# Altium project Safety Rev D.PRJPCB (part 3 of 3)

## Sheet SB_PG7.SCHDOC: (Title)
size B; PageSetup: Record=PageOptions|CenterHorizontal=True|CenterVertical=True|PrintScale=1.09|XCorrection=1.00|YCorrection=1.00|PrintKind=0|BorderSize=5000000|LeftOffset=0|BottomOffset=0|Orientation=2|PaperLength=1000|PaperWidth=1000|Scale=100|PaperSource=7|PrintQuality=-4|MediaType=1|DitherType=10|PaperKind=11x17|PrintScaleMode=1; Engineer: (Engineer); Organization: Institute for Astronomy; Address1: 640 N. Aohoku Place; Address2: Hilo, HI 96720; DocumentNumber: T3-2070; Revision: D; SheetNumber: 7; SheetTotal: 16
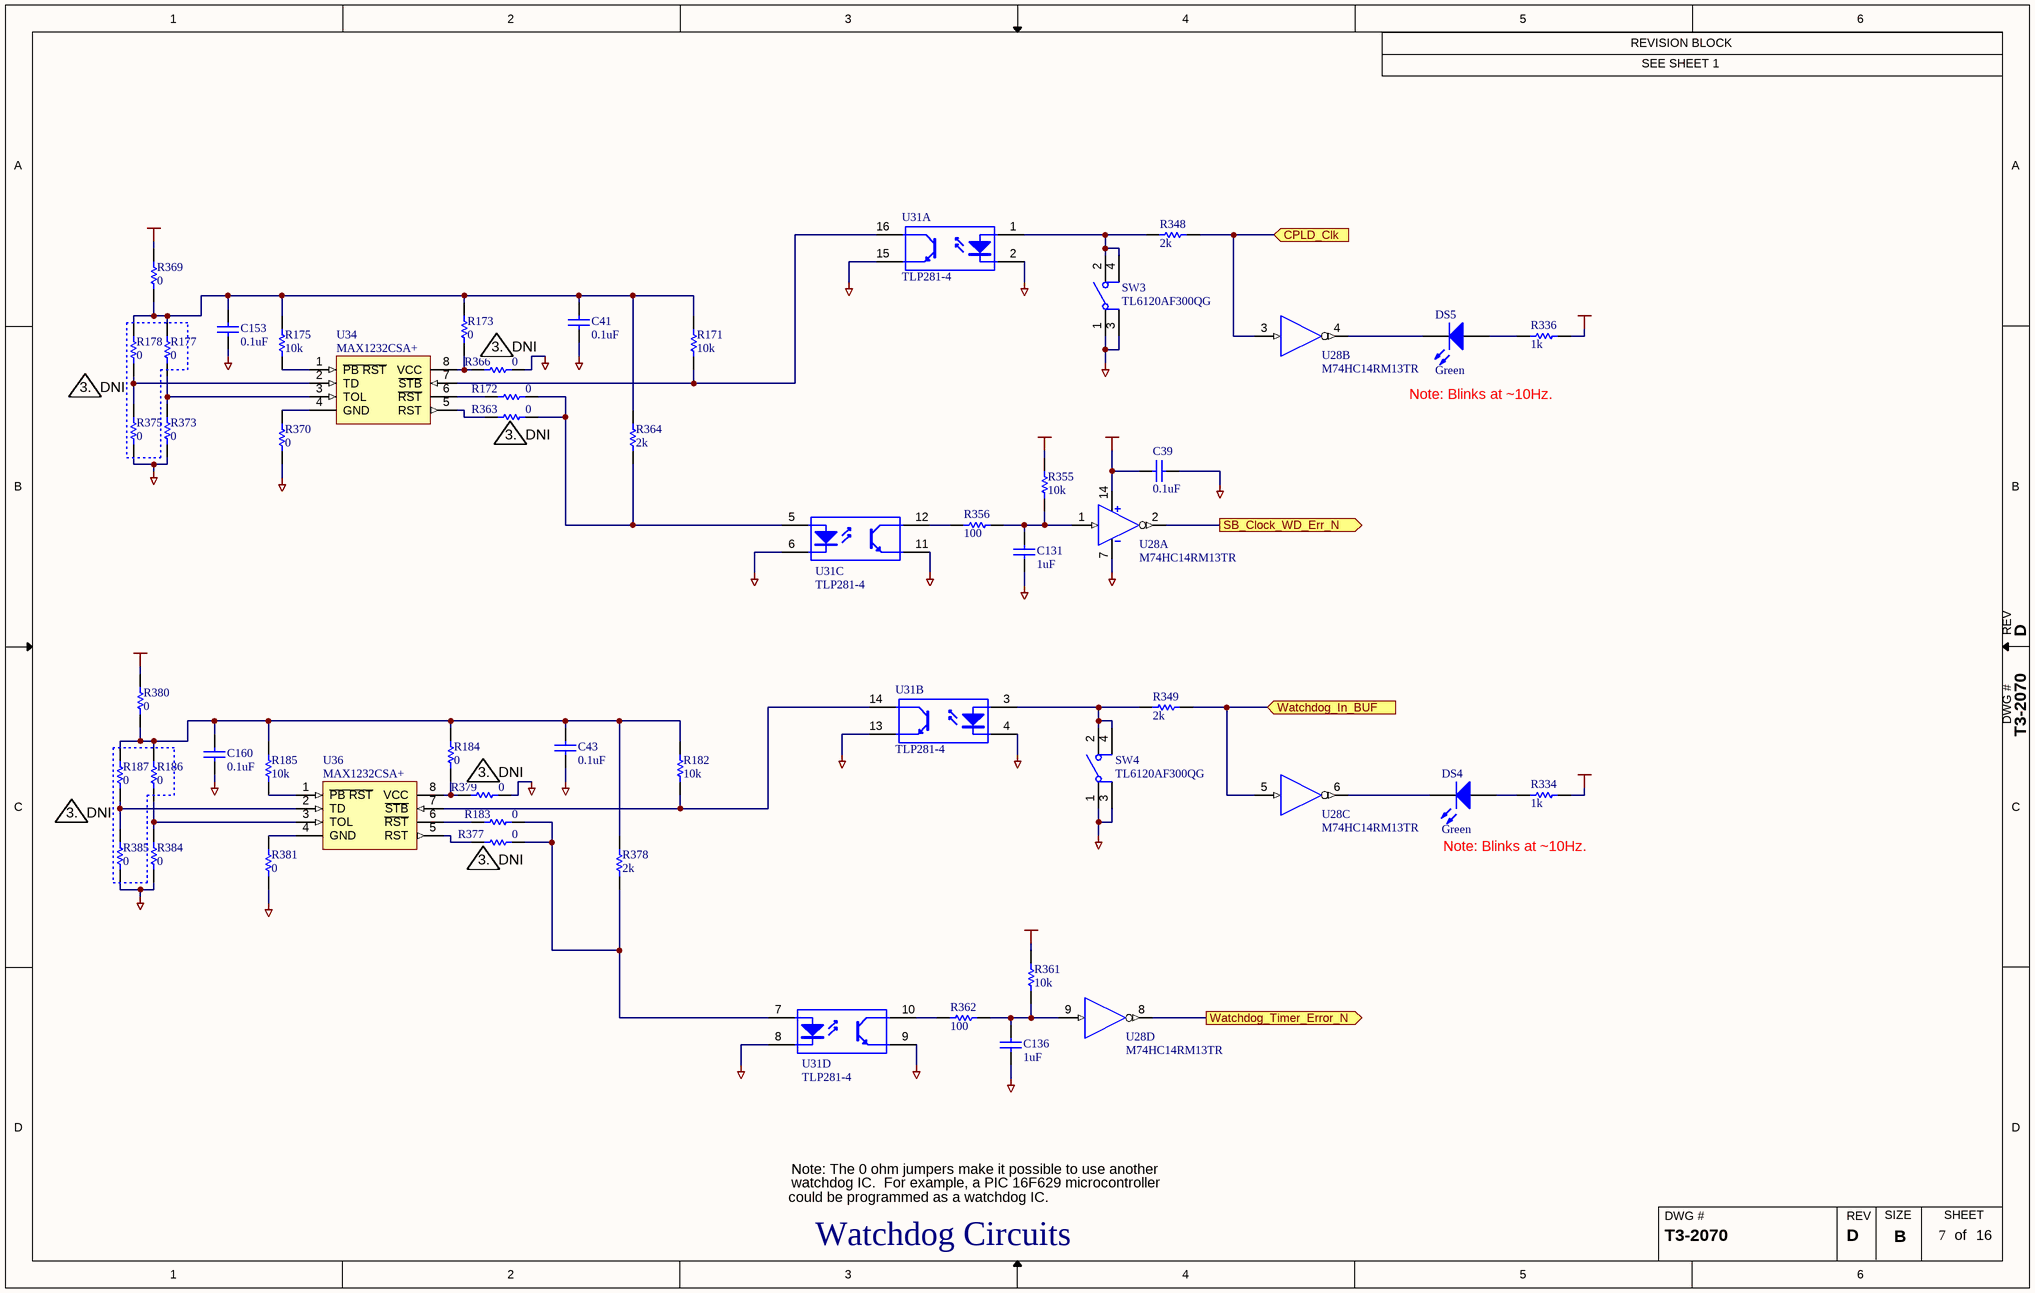
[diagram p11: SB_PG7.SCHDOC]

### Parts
(Parts that share a designator on the sheet are numbered #1, #2 ... from top to bottom, then left to right.)
C39  0.1uF  [1206]
C41  0.1uF  [1206]
C43  0.1uF  [1206]
C131  1uF  [1206]
C136  1uF  [1206]
C153  0.1uF  [1206]
C160  0.1uF  [1206]
DS4  value Green  [LED_1210]  (hidden comment: LTST-C930KGKT)
DS5  value Green  [LED_1210]  (hidden comment: LTST-C930KGKT)
Flag?#41  Flag#: 3.  Note: DNI  (graphical)
Flag?#42  Flag#: 3.  Note: DNI  (graphical)
Flag?#43  Flag#: 3.  Note: DNI  (graphical)
Flag?#44  Flag#: 3.  Note: DNI  (graphical)
Flag?#45  Flag#: 3.  Note: DNI  (graphical)
Flag?#46  Flag#: 3.  Note: DNI  (graphical)
R171  value 10k  [1206]  (hidden comment: 10000)
R172  value 0  [1206]  (hidden comment: 0_jumper)
R173  value 0  [1206]  (hidden comment: 0_jumper)
R175  value 10k  [1206]  (hidden comment: 10000)
R177  value 0  [1206]  (hidden comment: 0_jumper)  (no BOM)
R178  value 0  [1206]  (hidden comment: 0_jumper)  (no BOM)
R182  value 10k  [1206]  (hidden comment: 10000)
R183  value 0  [1206]  (hidden comment: 0_jumper)
R184  value 0  [1206]  (hidden comment: 0_jumper)
R185  value 10k  [1206]  (hidden comment: 10000)
R186  value 0  [1206]  (hidden comment: 0_jumper)  (no BOM)
R187  value 0  [1206]  (hidden comment: 0_jumper)  (no BOM)
R334  value 1k  [1206]  (hidden comment: 1000)
R336  value 1k  [1206]  (hidden comment: 1000)
R348  value 2k  [1206]  (hidden comment: 2000)
R349  value 2k  [1206]  (hidden comment: 2000)
R355  value 10k  [1206]  (hidden comment: 10000)
R356  100  [1206]
R361  value 10k  [1206]  (hidden comment: 10000)
R362  100  [1206]
R363  value 0  [1206]  (hidden comment: 0_jumper)  (no BOM)
R364  value 2k  [1206]  (hidden comment: 2000)
R366  value 0  [1206]  (hidden comment: 0_jumper)  (no BOM)
R369  value 0  [1206]  (hidden comment: 0_jumper)
R370  value 0  [1206]  (hidden comment: 0_jumper)
R373  value 0  [1206]  (hidden comment: 0_jumper)
R375  value 0  [1206]  (hidden comment: 0_jumper)  (no BOM)
R377  value 0  [1206]  (hidden comment: 0_jumper)  (no BOM)
R378  value 2k  [1206]  (hidden comment: 2000)
R379  value 0  [1206]  (hidden comment: 0_jumper)  (no BOM)
R380  value 0  [1206]  (hidden comment: 0_jumper)
R381  value 0  [1206]  (hidden comment: 0_jumper)
R384  value 0  [1206]  (hidden comment: 0_jumper)
R385  value 0  [1206]  (hidden comment: 0_jumper)  (no BOM)
SW3  TL6120AF300QG  [SWITCH_TL6120AF300QG]
SW4  TL6120AF300QG  [SWITCH_TL6120AF300QG]
U28  M74HC14RM13TR  [SOIC_14_Narrow]  (parts A,B,C,D of 6)
U31  TLP281-4  [SOIC_16_C5.85]  (parts A,B,C,D of 4)
U34  Part Number: MAX1232CSA+  [SOIC_8_NARROW]  (hidden comment: MAX1232ESA+)
U36  Part Number: MAX1232CSA+  [SOIC_8_NARROW]  (hidden comment: MAX1232ESA+)

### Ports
CPLD_Clk (in), SB_Clock_WD_Err_N (out), Watchdog_In_BUF (in), Watchdog_Timer_Error_N (out)

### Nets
+5V_DIG: C39.2 R334.2 R336.2 R355.2 R361.2 U28.14(VDD)
+5V_WD: R369.2 R380.2
DGND: C39.1 C131.1 C136.1 SW3.1(COMMON) SW3.3(COMMON) SW4.1(COMMON) SW4.3(COMMON) U28.7(GND) U31.2(K) U31.4(K) U31.9(E) U31.11(E)
WDGND: C41.1 C43.1 C153.1 C160.1 R366.1 R370.1 R373.1 R375.1 R379.1 R381.1 R384.1 R385.1 U31.6(K) U31.8(K) U31.13(E) U31.15(E)
CPLD_Clk: R348.1 U28.3(IN) ; port CPLD_Clk
SB_Clock_WD_Err_N: U28.2(~{OUT}) ; port SB_Clock_WD_Err_N
Watchdog_In_BUF: R349.1 U28.5(IN) ; port Watchdog_In_BUF
Watchdog_Timer_Error_N: U28.8(~{OUT}) ; port Watchdog_Timer_Error_N
NetC41_2: C41.2 C153.2 R171.2 R173.2 R175.2 R177.2 R178.2 R364.2 R369.1
NetC43_2: C43.2 C160.2 R182.2 R184.2 R185.2 R186.2 R187.2 R378.2 R380.1
NetC131_2: C131.2 R355.1 R356.1 U28.1(IN)
NetC136_2: C136.2 R361.1 R362.1 U28.9(IN)
NetDS4_A: DS4.A R334.1
NetDS4_K: DS4.K U28.6(~{OUT})
NetDS5_A: DS5.A R336.1
NetDS5_K: DS5.K U28.4(~{OUT})
NetR171_1: R171.1 U31.16(C) U34.7(~{STB})
NetR172_1: R172.1 R363.1 R364.1 U31.5(A)
NetR172_2: R172.2 U34.6(~{RST})
NetR173_1: R173.1 R366.2 U34.8(VCC)
NetR175_1: R175.1 U34.1(~{PB_RST})
NetR177_1: R177.1 R373.2 U34.3(TOL)
NetR178_1: R178.1 R375.2 U34.2(TD)
NetR182_1: R182.1 U31.14(C) U36.7(~{STB})
NetR183_1: R183.1 R377.1 R378.1 U31.7(A)
NetR183_2: R183.2 U36.6(~{RST})
NetR184_1: R184.1 R379.2 U36.8(VCC)
NetR185_1: R185.1 U36.1(~{PB_RST})
NetR186_1: R186.1 R384.2 U36.3(TOL)
NetR187_1: R187.1 R385.2 U36.2(TD)
NetR348_2: R348.2 SW3.2(NO) SW3.4(NO) U31.1(A)
NetR349_2: R349.2 SW4.2(NO) SW4.4(NO) U31.3(A)
NetR356_2: R356.2 U31.12(C)
NetR362_2: R362.2 U31.10(C)
NetR363_2: R363.2 U34.5(RST)
NetR370_2: R370.2 U34.4(GND)
NetR377_2: R377.2 U36.5(RST)
NetR381_2: R381.2 U36.4(GND)

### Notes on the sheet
- Note: Blinks at
  0Hz.
- Note: The 0 ohm jumpers make it possible to use another
- could be programmed as a watchdog IC.
- watchdog IC.  For example, a PIC 16F629 microcontroller
- Watchdog Circuits

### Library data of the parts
C39 C41 C43 C153 C160 = 0.1uF: Ceramic Chip Capacitor, 0.1uF, 50V, 10%, X7R; Part Number: C1206C104K5RACTU; Manufacturer: Kemet; BOM_IGNORE: False
C131 C136 = 1uF: Ceramic Chip Capacitor, 1uF, 50V, 10%, X7R; Part Number: C1206F105K5RACTU; Manufacturer: Kemet; BOM_IGNORE: False
DS4 DS5 = LTST-C930KGKT: LED, Green, Dome, 1210 SMD; Manufacturer: Lite-On Inc; BOM_IGNORE: FALSE
Flag?#41-Flag?#46 = Flag
R171 R175 R182 R185 R355 R361 = 10000: Thick Film Chip Resistor, 10k Ohm, 1% Tolerance, 1206 Size, 0.25 W; Part Number: ERJ-8ENF1002V; Manufacturer: Panasonic; Power Rating: 0.25W
R172 R173 R177 R178 R183 R184 R186 R187 R363 R366 R369 R370 R373 R375 R377 R379-R381 R384 R385 = 0_jumper: Thick Film Chip Resistor, 0 Ohm, 1206 Size, 0.25 W; Part Number: ERJ-8GEY0R00V; Manufacturer: Panasonic; Tolerance: 1%; Power Rating: 0.25W
R334 R336 = 1000: Thick Film Chip Resistor, 1k Ohm, 1% Tolerance, 1206 Size, 0.25 W; Part Number: ERJ-8ENF1001V; Manufacturer: Panasonic; Power Rating: 0.25W
R348 R349 R364 R378 = 2000: Thick Film Chip Resistor, 2k Ohm, 1% Tolerance, 1206 Size, 0.25 W; Part Number: ERJ-8ENF2001V; Manufacturer: Panasonic; Power Rating: 0.25W
R356 R362 = 100: Thick Film Chip Resistor, 100 Ohm, 1% Tolerance, 1206 Size, 0.25 W; Part Number: ERJ-8ENF1000V; Manufacturer: Panasonic; Power Rating: 0.25W
SW3 SW4 = TL6120AF300QG: Switch, Tactile, SPST, NO; Manufacturer: E-Switch
U28 = M74HC14RM13TR: Hex Schmitt-Trigger Inverter; Manufacturer: STMicroelectronics
U31 = TLP281-4: Photocoupler; Manufacturer: Toshiba
U34 U36 = MAX1232ESA+: IC MPU SUPERVISORY CIRCUIT 8SOIC; Manufacturer: Maxim

## Sheet SB_PG8.SCHDOC: (Title)
size B; PageSetup: Record=PageOptions|CenterHorizontal=True|CenterVertical=True|PrintScale=1.09|XCorrection=1.00|YCorrection=1.00|PrintKind=0|BorderSize=5000000|LeftOffset=0|BottomOffset=0|Orientation=2|PaperLength=1000|PaperWidth=1000|Scale=100|PaperSource=7|PrintQuality=-4|MediaType=1|DitherType=10|PaperKind=11x17|PrintScaleMode=1; Engineer: (Engineer); Organization: Institute for Astronomy; Address1: 640 N. Aohoku Place; Address2: Hilo, HI 96720; DocumentNumber: T3-2070; Revision: D; SheetNumber: 8; SheetTotal: 16
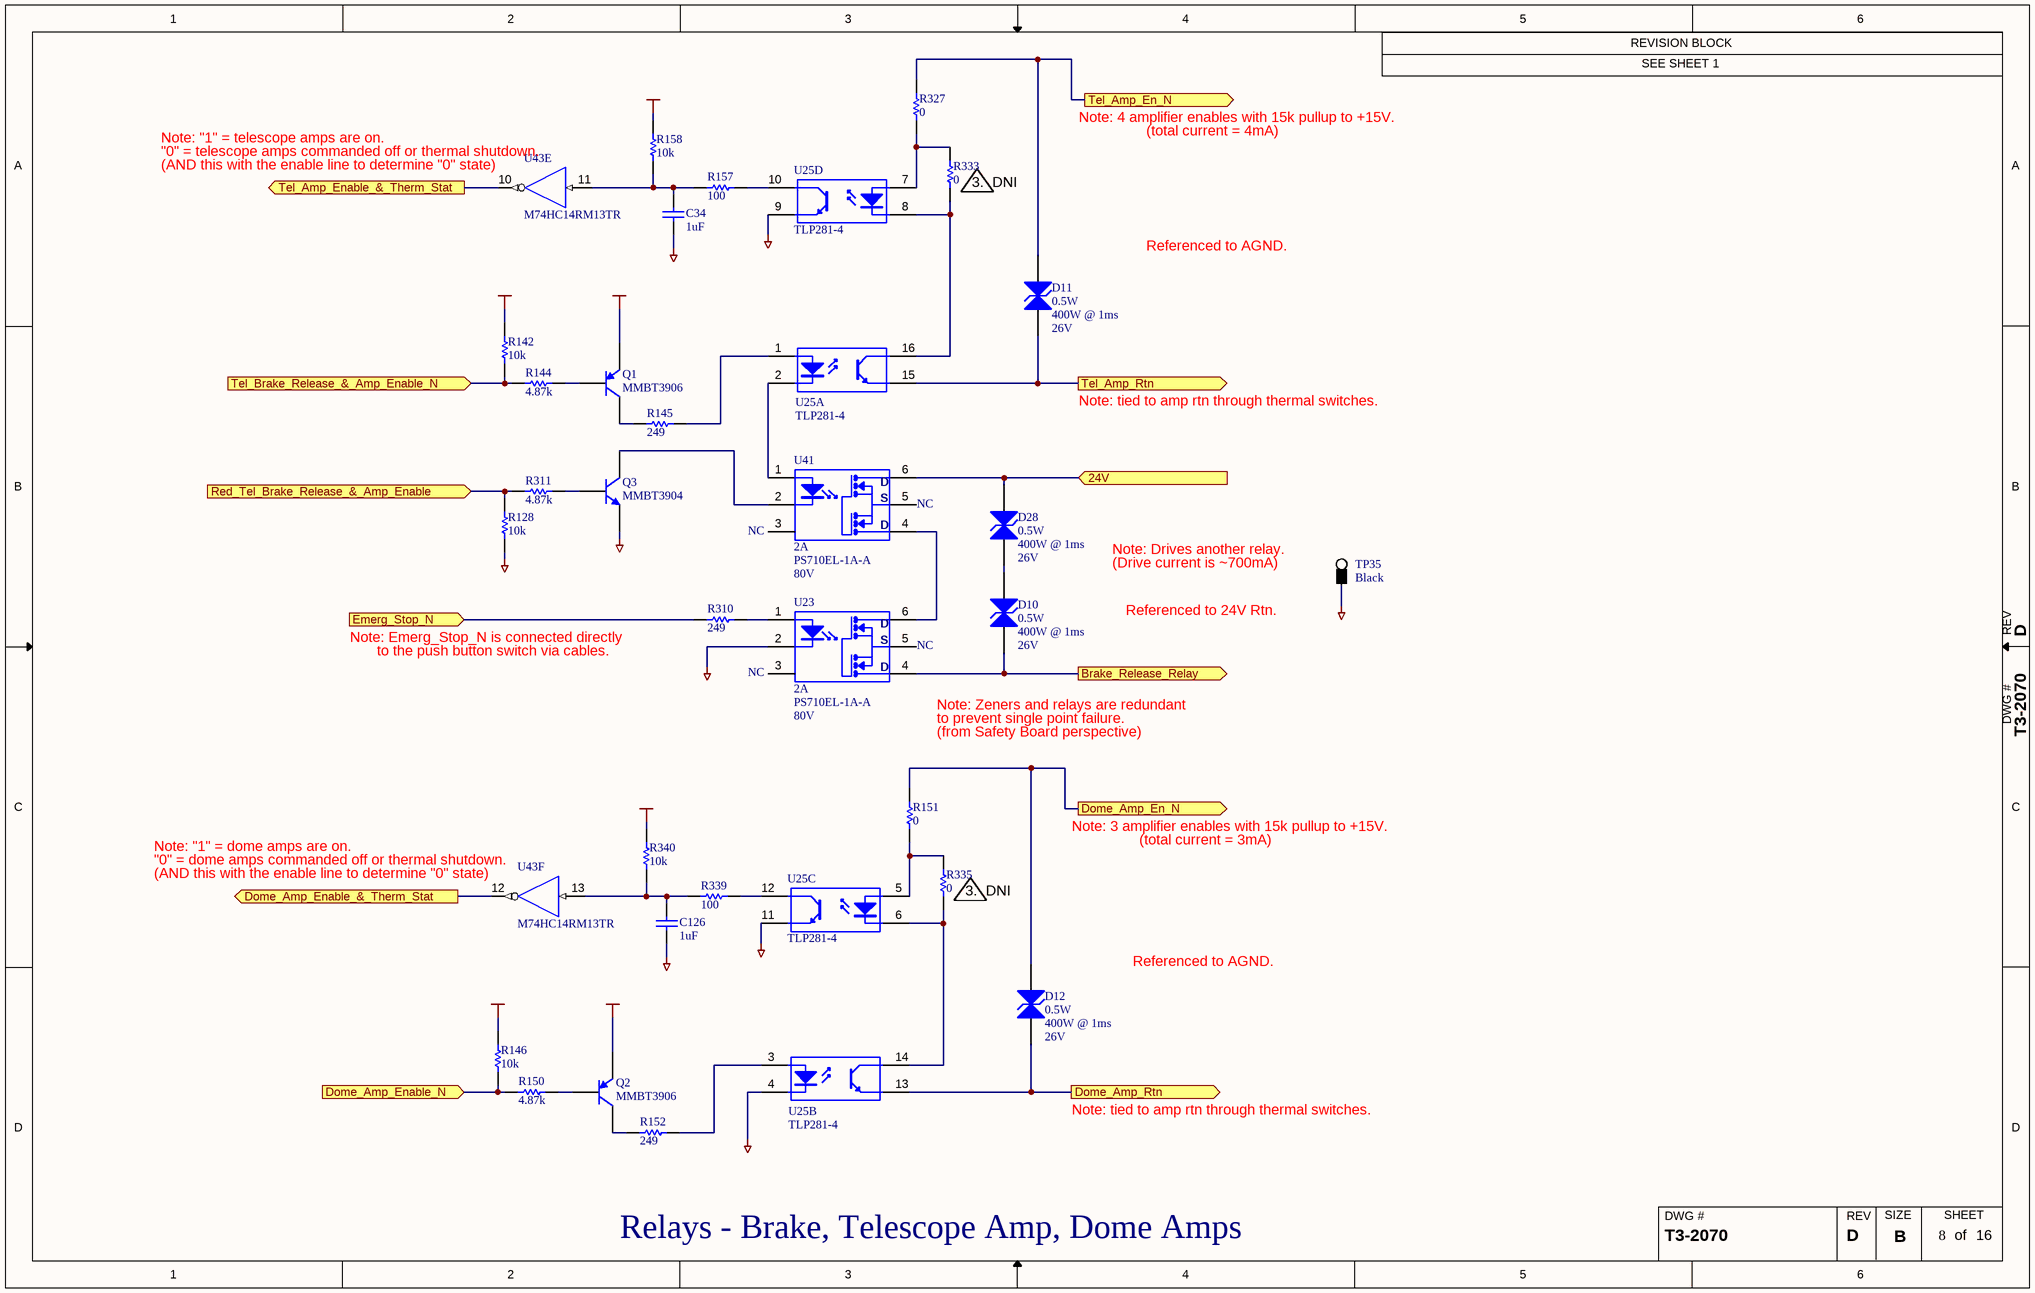
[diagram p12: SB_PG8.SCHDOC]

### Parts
(Parts that share a designator on the sheet are numbered #1, #2 ... from top to bottom, then left to right.)
C34  1uF  [1206]
C126  1uF  [1206]
D10  value 26V  Power: 0.5W  Peak Power: 400W @ 1ms  [DO-214AC (SMA)]  (hidden comment: SMAJ26CA)
D11  value 26V  Power: 0.5W  Peak Power: 400W @ 1ms  [DO-214AC (SMA)]  (hidden comment: SMAJ26CA)
D12  value 26V  Power: 0.5W  Peak Power: 400W @ 1ms  [DO-214AC (SMA)]  (hidden comment: SMAJ26CA)
D28  value 26V  Power: 0.5W  Peak Power: 400W @ 1ms  [DO-214AC (SMA)]  (hidden comment: SMAJ26CA)
Flag?#47  Flag#: 3.  Note: DNI  (graphical)
Flag?#48  Flag#: 3.  Note: DNI  (graphical)
Q1  MMBT3906  [SOT23]
Q2  MMBT3906  [SOT23]
Q3  MMBT3904  [SOT23]
R128  value 10k  [1206]  (hidden comment: 10000)
R142  value 10k  [1206]  (hidden comment: 10000)
R144  value 4.87k  [1206]  (hidden comment: 4870)
R145  249  [1206]
R146  value 10k  [1206]  (hidden comment: 10000)
R150  value 4.87k  [1206]  (hidden comment: 4870)
R151  value 0  [1206]  (hidden comment: 0_jumper)
R152  249  [1206]
R157  100  [1206]
R158  value 10k  [1206]  (hidden comment: 10000)
R310  249  [1206]
R311  value 4.87k  [1206]  (hidden comment: 4870)
R327  value 0  [1206]  (hidden comment: 0_jumper)
R333  value 0  [1206]  (hidden comment: 0_jumper)  (no BOM)
R335  value 0  [1206]  (hidden comment: 0_jumper)  (no BOM)
R339  100  [1206]
R340  value 10k  [1206]  (hidden comment: 10000)
TP35  value Black  [TP_COMPACT]  (hidden comment: TP_5006)
U23  Current: 2A  Voltage: 80V  [SO_6_254P]  (hidden comment: PS710EL-1A-A)
U25  TLP281-4  [SOIC_16_C5.85]  (parts A,B,C,D of 4)
U41  Current: 2A  Voltage: 80V  [SO_6_254P]  (hidden comment: PS710EL-1A-A)
U43  M74HC14RM13TR  [SOIC_14_Narrow]  (parts E,F of 6)

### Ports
24V (in), Brake_Release_Relay (out), Dome_Amp_En_N (out), Dome_Amp_Enable_&_Therm_Stat (out), Dome_Amp_Enable_N (in), Dome_Amp_Rtn (out), Emerg_Stop_N (in), Red_Tel_Brake_Release_&_Amp_Enable (in), Tel_Amp_En_N (out), Tel_Amp_Enable_&_Therm_Stat (out), Tel_Amp_Rtn (out), Tel_Brake_Release_&_Amp_Enable_N (in)

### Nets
24VGND: TP35.1
+5V_DIG: Q1.2(E) Q2.2(E) R142.1 R146.2 R158.2 R340.2
DGND: C34.1 C126.1 Q3.2(E) R128.2 U25.4(K) U25.9(E) U25.11(E)
SEGND: U23.2(K)
24V: D28.K U41.6(DRAIN) ; port 24V
Brake Enable Relay: D10.A U23.4(DRAIN) ; port Brake_Release_Relay
Dome Amp: D12.K R151.1 ; port Dome_Amp_En_N
Dome Amp Ret: D12.A U25.13(E) ; port Dome_Amp_Rtn
Dome_Amp_Enable_&_Therm_Stat: U43.12(~{OUT}) ; port Dome_Amp_Enable_&_Therm_Stat
Dome_Amp_Enable_N: R146.1 R150.2 ; port Dome_Amp_Enable_N
Emerg Stop: R310.2 ; port Emerg_Stop_N
Red_Tel_Brake_Release_&_Amp_Enable: R128.1 R311.2 ; port Red_Tel_Brake_Release_&_Amp_Enable
Tel Amp: D11.K R327.1 ; port Tel_Amp_En_N
Tel Amp Ret: D11.A U25.15(E) ; port Tel_Amp_Rtn
Tel_Amp_Enable_&_Therm_Stat: U43.10(~{OUT}) ; port Tel_Amp_Enable_&_Therm_Stat
Tel_Brake_Release_&_Amp_Enable_N: R142.2 R144.2 ; port Tel_Brake_Release_&_Amp_Enable_N
NetC34_2: C34.2 R157.2 R158.1 U43.11(IN)
NetC126_2: C126.2 R339.2 R340.1 U43.13(IN)
NetD10_K: D10.K D28.A
NetQ1_1: Q1.1(B) R144.1
NetQ1_3: Q1.3(C) R145.2
NetQ2_1: Q2.1(B) R150.1
NetQ2_3: Q2.3(C) R152.2
NetQ3_1: Q3.1(B) R311.1
NetQ3_3: Q3.3(C) U41.2(K)
NetR145_1: R145.1 U25.1(A)
NetR151_2: R151.2 R335.1 U25.5(A)
NetR152_1: R152.1 U25.3(A)
NetR157_1: R157.1 U25.10(C)
NetR310_1: R310.1 U23.1(A)
NetR327_2: R327.2 R333.1 U25.7(A)
NetR333_2: R333.2 U25.8(K) U25.16(C)
NetR335_2: R335.2 U25.6(K) U25.14(C)
NetR339_1: R339.1 U25.12(C)
NetU23_6: U23.6(DRAIN) U41.4(DRAIN)
NetU25_2: U25.2(K) U41.1(A)

Not connected (* = marked no-connect by the designer): U23 3(NC) 5(SOURCE); U41 3(NC) 5(SOURCE)

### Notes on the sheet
- Note: "1" = telescope amps are on.
- (near U43) "0" = telescope amps commanded off or thermal shutdown.
- Note: 4 amplifier enables with 15k pullup to +15V.
- (total current = 4mA)
- (near U43) (AND this with the enable line to determine "0" state)
- Referenced to AGND.
- Note: tied to amp rtn through thermal switches.
- (near U41) NC
- (near TP35) Note: Drives another relay.
- (near TP35) (Drive current is ~700mA)
- Note: Emerg_Stop_N is connected directly
- Referenced to 24V Rtn.
- to the push button switch via cables.
- NC
- (near U23) NC
- Note: Zeners and relays are redundant
- to prevent single point failure.
- (from Safety Board perspective)
- Note: 3 amplifier enables with 15k pullup to +15V.
- Note: "1" = dome amps are on.
- (near U43) "0" = dome amps commanded off or thermal shutdown.
- (total current = 3mA)
- Relays - Brake, Telescope Amp, Dome Amps

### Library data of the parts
C34 C126 = 1uF: as C131 on sheet SB_PG7
D10-D12 D28 = SMAJ26CA: TVS 400W 26V BIDIRECT SMA; Manufacturer: Diodes Inc.
Flag?#47 Flag?#48 = Flag
Q1 Q2 = MMBT3906: PNP Switching Transistor; Manufacturer: Fairchild Semiconductor
Q3 = MMBT3904: NPN Switching Transistor; Manufacturer: Fairchild Semiconductor
R128 R142 R146 R158 R340 = 10000: as R171 on sheet SB_PG7
R144 R150 R311 = 4870: Thick Film Chip Resistor, 4.87k Ohm, 1% Tolerance, 1206 Size, 0.25 W; Part Number: ERJ-8ENF4871V; Manufacturer: Panasonic; Power Rating: 0.25W
R145 R152 R310 = 249: Thick Film Chip Resistor, 249 Ohm, 1% Tolerance, 1206 Size, 0.25 W; Part Number: ERJ-8ENF2490V; Manufacturer: Panasonic; Power Rating: 0.25W
R151 R327 R333 R335 = 0_jumper: as R172 on sheet SB_PG7
R157 R339 = 100: as R356 on sheet SB_PG7
TP35 = TP_5006: Black, Compact Test Point, Thru Hole, Loop; Part Number: 5006; Manufacturer: Keystone; BOM_IGNORE: FALSE
U23 U41 = PS710EL-1A-A: Solid State Relay, 2A, 80V; Manufacturer: NEC
U25 = TLP281-4: Photocoupler; Manufacturer: Toshiba
U43 = M74HC14RM13TR: as U28 on sheet SB_PG7

## Sheet SB_PG9.SCHDOC: (Title)
size B; PageSetup: Record=PageOptions|CenterHorizontal=True|CenterVertical=True|PrintScale=1.09|XCorrection=1.00|YCorrection=1.00|PrintKind=0|BorderSize=5000000|LeftOffset=0|BottomOffset=0|Orientation=2|PaperLength=1000|PaperWidth=1000|Scale=100|PaperSource=7|PrintQuality=-4|MediaType=1|DitherType=10|PaperKind=11x17|PrintScaleMode=1; Engineer: (Engineer); Organization: Institute for Astronomy; Address1: 640 N. Aohoku Place; Address2: Hilo, HI 96720; DocumentNumber: T3-2070; Revision: D; SheetNumber: 9; SheetTotal: 16
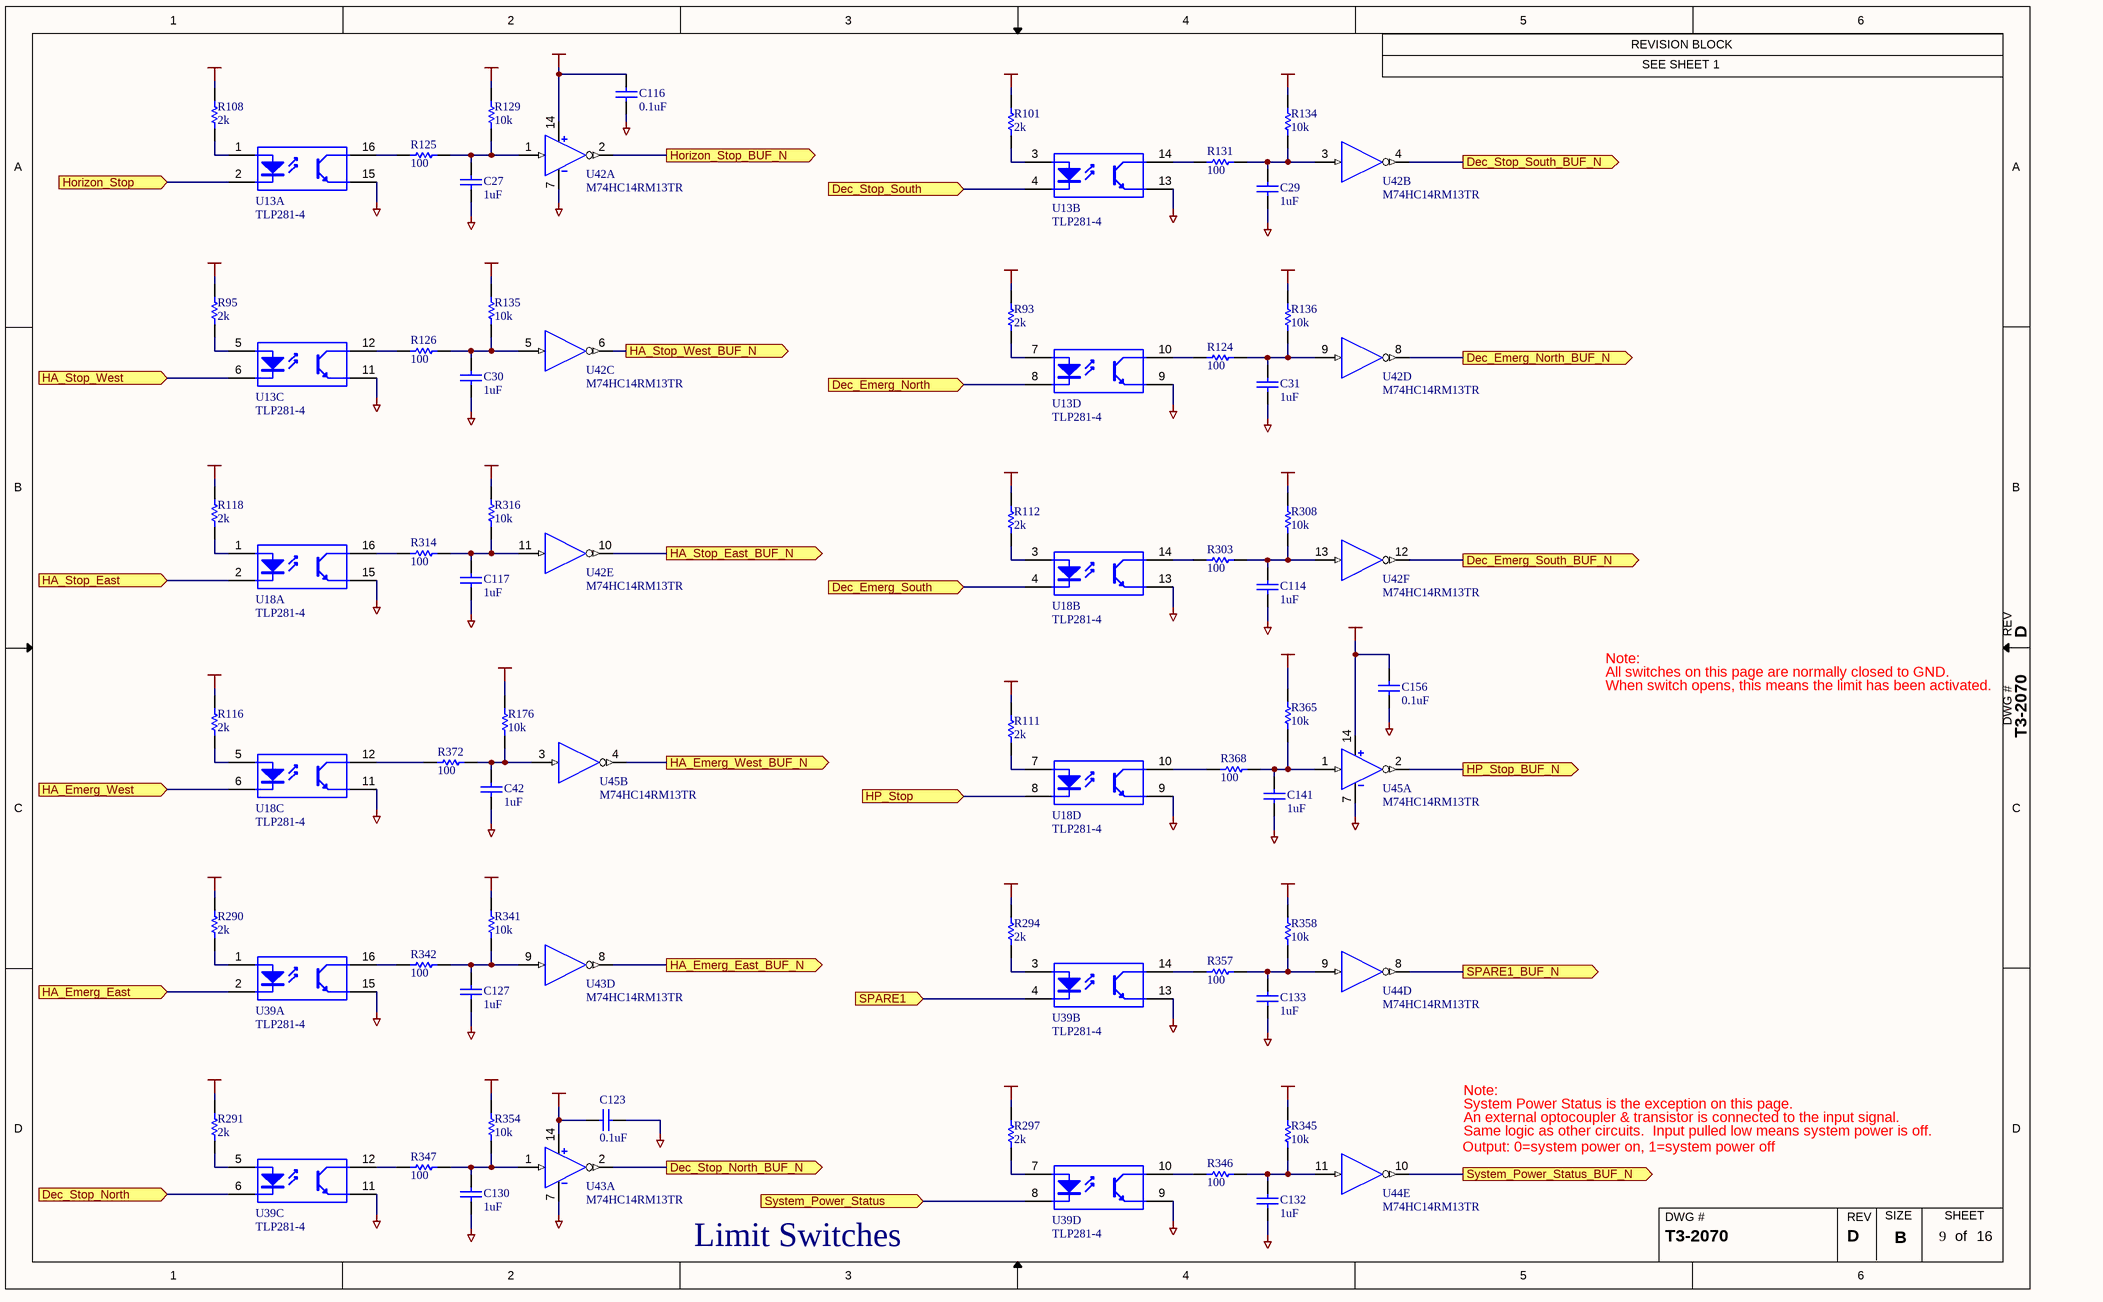
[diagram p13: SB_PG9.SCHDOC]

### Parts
C27  1uF  [1206]
C29  1uF  [1206]
C30  1uF  [1206]
C31  1uF  [1206]
C42  1uF  [1206]
C114  1uF  [1206]
C116  0.1uF  [1206]
C117  1uF  [1206]
C123  0.1uF  [1206]
C127  1uF  [1206]
C130  1uF  [1206]
C132  1uF  [1206]
C133  1uF  [1206]
C141  1uF  [1206]
C156  0.1uF  [1206]
R93  value 2k  [1206]  (hidden comment: 2000)
R95  value 2k  [1206]  (hidden comment: 2000)
R101  value 2k  [1206]  (hidden comment: 2000)
R108  value 2k  [1206]  (hidden comment: 2000)
R111  value 2k  [1206]  (hidden comment: 2000)
R112  value 2k  [1206]  (hidden comment: 2000)
R116  value 2k  [1206]  (hidden comment: 2000)
R118  value 2k  [1206]  (hidden comment: 2000)
R124  100  [1206]
R125  100  [1206]
R126  100  [1206]
R129  value 10k  [1206]  (hidden comment: 10000)
R131  100  [1206]
R134  value 10k  [1206]  (hidden comment: 10000)
R135  value 10k  [1206]  (hidden comment: 10000)
R136  value 10k  [1206]  (hidden comment: 10000)
R176  value 10k  [1206]  (hidden comment: 10000)
R290  value 2k  [1206]  (hidden comment: 2000)
R291  value 2k  [1206]  (hidden comment: 2000)
R294  value 2k  [1206]  (hidden comment: 2000)
R297  value 2k  [1206]  (hidden comment: 2000)
R303  100  [1206]
R308  value 10k  [1206]  (hidden comment: 10000)
R314  100  [1206]
R316  value 10k  [1206]  (hidden comment: 10000)
R341  value 10k  [1206]  (hidden comment: 10000)
R342  100  [1206]
R345  value 10k  [1206]  (hidden comment: 10000)
R346  100  [1206]
R347  100  [1206]
R354  value 10k  [1206]  (hidden comment: 10000)
R357  100  [1206]
R358  value 10k  [1206]  (hidden comment: 10000)
R365  value 10k  [1206]  (hidden comment: 10000)
R368  100  [1206]
R372  100  [1206]
U13  TLP281-4  [SOIC_16_C5.85]  (parts A,B,C,D of 4)
U18  TLP281-4  [SOIC_16_C5.85]  (parts A,B,C,D of 4)
U39  TLP281-4  [SOIC_16_C5.85]  (parts A,B,C,D of 4)
U42  M74HC14RM13TR  [SOIC_14_Narrow]  (parts A,B,C,D,E,F of 6)
U43  M74HC14RM13TR  [SOIC_14_Narrow]  (parts A,D of 6)
U44  M74HC14RM13TR  [SOIC_14_Narrow]  (parts D,E of 6)
U45  M74HC14RM13TR  [SOIC_14_Narrow]  (parts A,B of 6)

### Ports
Dec_Emerg_North (in), Dec_Emerg_North_BUF_N (out), Dec_Emerg_South (in), Dec_Emerg_South_BUF_N (out), Dec_Stop_North (in), Dec_Stop_North_BUF_N (out), Dec_Stop_South (in), Dec_Stop_South_BUF_N (out), HA_Emerg_East (in), HA_Emerg_East_BUF_N (out), HA_Emerg_West (in), HA_Emerg_West_BUF_N (out), HA_Stop_East (in), HA_Stop_East_BUF_N (out), HA_Stop_West (in), HA_Stop_West_BUF_N (out), Horizon_Stop (in), Horizon_Stop_BUF_N (out), HP_Stop (in), HP_Stop_BUF_N (out), SPARE1 (in), SPARE1_BUF_N (out), System_Power_Status (in), System_Power_Status_BUF_N (out)

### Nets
+5V_DIG: C116.2 C123.2 C156.2 R129.2 R134.2 R135.2 R136.2 R176.2 R308.2 R316.2 R341.2 R345.2 R354.2 R358.2 R365.2 U42.14(VDD) U43.14(VDD) U45.14(VDD)
+5V_SE: R93.2 R95.2 R101.2 R108.2 R111.2 R112.2 R116.2 R118.2 R290.2 R291.2 R294.2 R297.2
DGND: C27.1 C29.1 C30.1 C31.1 C42.1 C114.1 C116.1 C117.1 C123.1 C127.1 C130.1 C132.1 C133.1 C141.1 C156.1 U13.9(E) U13.11(E) U13.13(E) U13.15(E) U18.9(E) U18.11(E) U18.13(E) U18.15(E) U39.9(E) U39.11(E) U39.13(E) U39.15(E) U42.7(GND) U43.7(GND) U45.7(GND)
Dec Emerg N: U13.8(K) ; port Dec_Emerg_North
Dec Emerg S: U18.4(K) ; port Dec_Emerg_South
Dec Stop N: U39.6(K) ; port Dec_Stop_North
Dec Stop S: U13.4(K) ; port Dec_Stop_South
Dec_Emerg_North_BUF_N: U42.8(~{OUT}) ; port Dec_Emerg_North_BUF_N
Dec_Emerg_South_BUF_N: U42.12(~{OUT}) ; port Dec_Emerg_South_BUF_N
Dec_Stop_North_BUF_N: U43.2(~{OUT}) ; port Dec_Stop_North_BUF_N
Dec_Stop_South_BUF_N: U42.4(~{OUT}) ; port Dec_Stop_South_BUF_N
HA Emerg E: U39.2(K) ; port HA_Emerg_East
HA Emerg W: U18.6(K) ; port HA_Emerg_West
HA Stop E: U18.2(K) ; port HA_Stop_East
HA Stop W: U13.6(K) ; port HA_Stop_West
HA_Emerg_East_BUF_N: U43.8(~{OUT}) ; port HA_Emerg_East_BUF_N
HA_Emerg_West_BUF_N: U45.4(~{OUT}) ; port HA_Emerg_West_BUF_N
HA_Stop_East_BUF_N: U42.10(~{OUT}) ; port HA_Stop_East_BUF_N
HA_Stop_West_BUF_N: U42.6(~{OUT}) ; port HA_Stop_West_BUF_N
Horizon Stop: U13.2(K) ; port Horizon_Stop
Horizon_Stop_BUF_N: U42.2(~{OUT}) ; port Horizon_Stop_BUF_N
HP Stop: U18.8(K) ; port HP_Stop
HP_Stop_BUF_N: U45.2(~{OUT}) ; port HP_Stop_BUF_N
SPARE1_BUF_N: U44.8(~{OUT}) ; port SPARE1_BUF_N
Spare In 1: U39.4(K) ; port SPARE1
System Power Status: U39.8(K) ; port System_Power_Status
System_Power_Status_BUF_N: U44.10(~{OUT}) ; port System_Power_Status_BUF_N
NetC27_2: C27.2 R125.1 R129.1 U42.1(IN)
NetC29_2: C29.2 R131.1 R134.1 U42.3(IN)
NetC30_2: C30.2 R126.1 R135.1 U42.5(IN)
NetC31_2: C31.2 R124.1 R136.1 U42.9(IN)
NetC42_2: C42.2 R176.1 R372.1 U45.3(IN)
NetC114_2: C114.2 R303.1 R308.1 U42.13(IN)
NetC117_2: C117.2 R314.1 R316.1 U42.11(IN)
NetC127_2: C127.2 R341.1 R342.1 U43.9(IN)
NetC130_2: C130.2 R347.1 R354.1 U43.1(IN)
NetC132_2: C132.2 R345.1 R346.1 U44.11(IN)
NetC133_2: C133.2 R357.1 R358.1 U44.9(IN)
NetC141_2: C141.2 R365.1 R368.1 U45.1(IN)
NetR93_1: R93.1 U13.7(A)
NetR95_1: R95.1 U13.5(A)
NetR101_1: R101.1 U13.3(A)
NetR108_1: R108.1 U13.1(A)
NetR111_1: R111.1 U18.7(A)
NetR112_1: R112.1 U18.3(A)
NetR116_1: R116.1 U18.5(A)
NetR118_1: R118.1 U18.1(A)
NetR124_2: R124.2 U13.10(C)
NetR125_2: R125.2 U13.16(C)
NetR126_2: R126.2 U13.12(C)
NetR131_2: R131.2 U13.14(C)
NetR290_1: R290.1 U39.1(A)
NetR291_1: R291.1 U39.5(A)
NetR294_1: R294.1 U39.3(A)
NetR297_1: R297.1 U39.7(A)
NetR303_2: R303.2 U18.14(C)
NetR314_2: R314.2 U18.16(C)
NetR342_2: R342.2 U39.16(C)
NetR346_2: R346.2 U39.10(C)
NetR347_2: R347.2 U39.12(C)
NetR357_2: R357.2 U39.14(C)
NetR368_2: R368.2 U18.10(C)
NetR372_2: R372.2 U18.12(C)

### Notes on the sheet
- All switches on this page are normally closed to GND.
- Note:
- When switch opens, this means the limit has been activated.
- System Power Status is the exception on this page.
- Output: 0=system power on, 1=system power off
- An external optocoupler & transistor is connected to the input signal.
- Same logic as other circuits.  Input pulled low means system power is off.
- Limit Switches

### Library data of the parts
C27 C29-C31 C42 C114 C117 C127 C130 C132 C133 C141 = 1uF: as C131 on sheet SB_PG7
C116 C123 C156 = 0.1uF: as C39 on sheet SB_PG7
R93 R95 R101 R108 R111 R112 R116 R118 R290 R291 R294 R297 = 2000: as R348 on sheet SB_PG7
R124-R126 R131 R303 R314 R342 R346 R347 R357 R368 R372 = 100: as R356 on sheet SB_PG7
R129 R134-R136 R176 R308 R316 R341 R345 R354 R358 R365 = 10000: as R171 on sheet SB_PG7
U13 U18 U39 = TLP281-4: Photocoupler; Manufacturer: Toshiba
U42-U45 = M74HC14RM13TR: as U28 on sheet SB_PG7

## Sheet SB_PG10.SCHDOC: (Title)
size B; PageSetup: Record=PageOptions|CenterHorizontal=True|CenterVertical=True|PrintScale=1.09|XCorrection=1.00|YCorrection=1.00|PrintKind=0|BorderSize=5000000|LeftOffset=0|BottomOffset=0|Orientation=2|PaperLength=1000|PaperWidth=1000|Scale=100|PaperSource=7|PrintQuality=-4|MediaType=1|DitherType=10|PaperKind=11x17|PrintScaleMode=1; Engineer: (Engineer); Organization: Institute for Astronomy; Address1: 640 N. Aohoku Place; Address2: Hilo, HI 96720; DocumentNumber: T3-2070; Revision: D; SheetNumber: 10; SheetTotal: 16
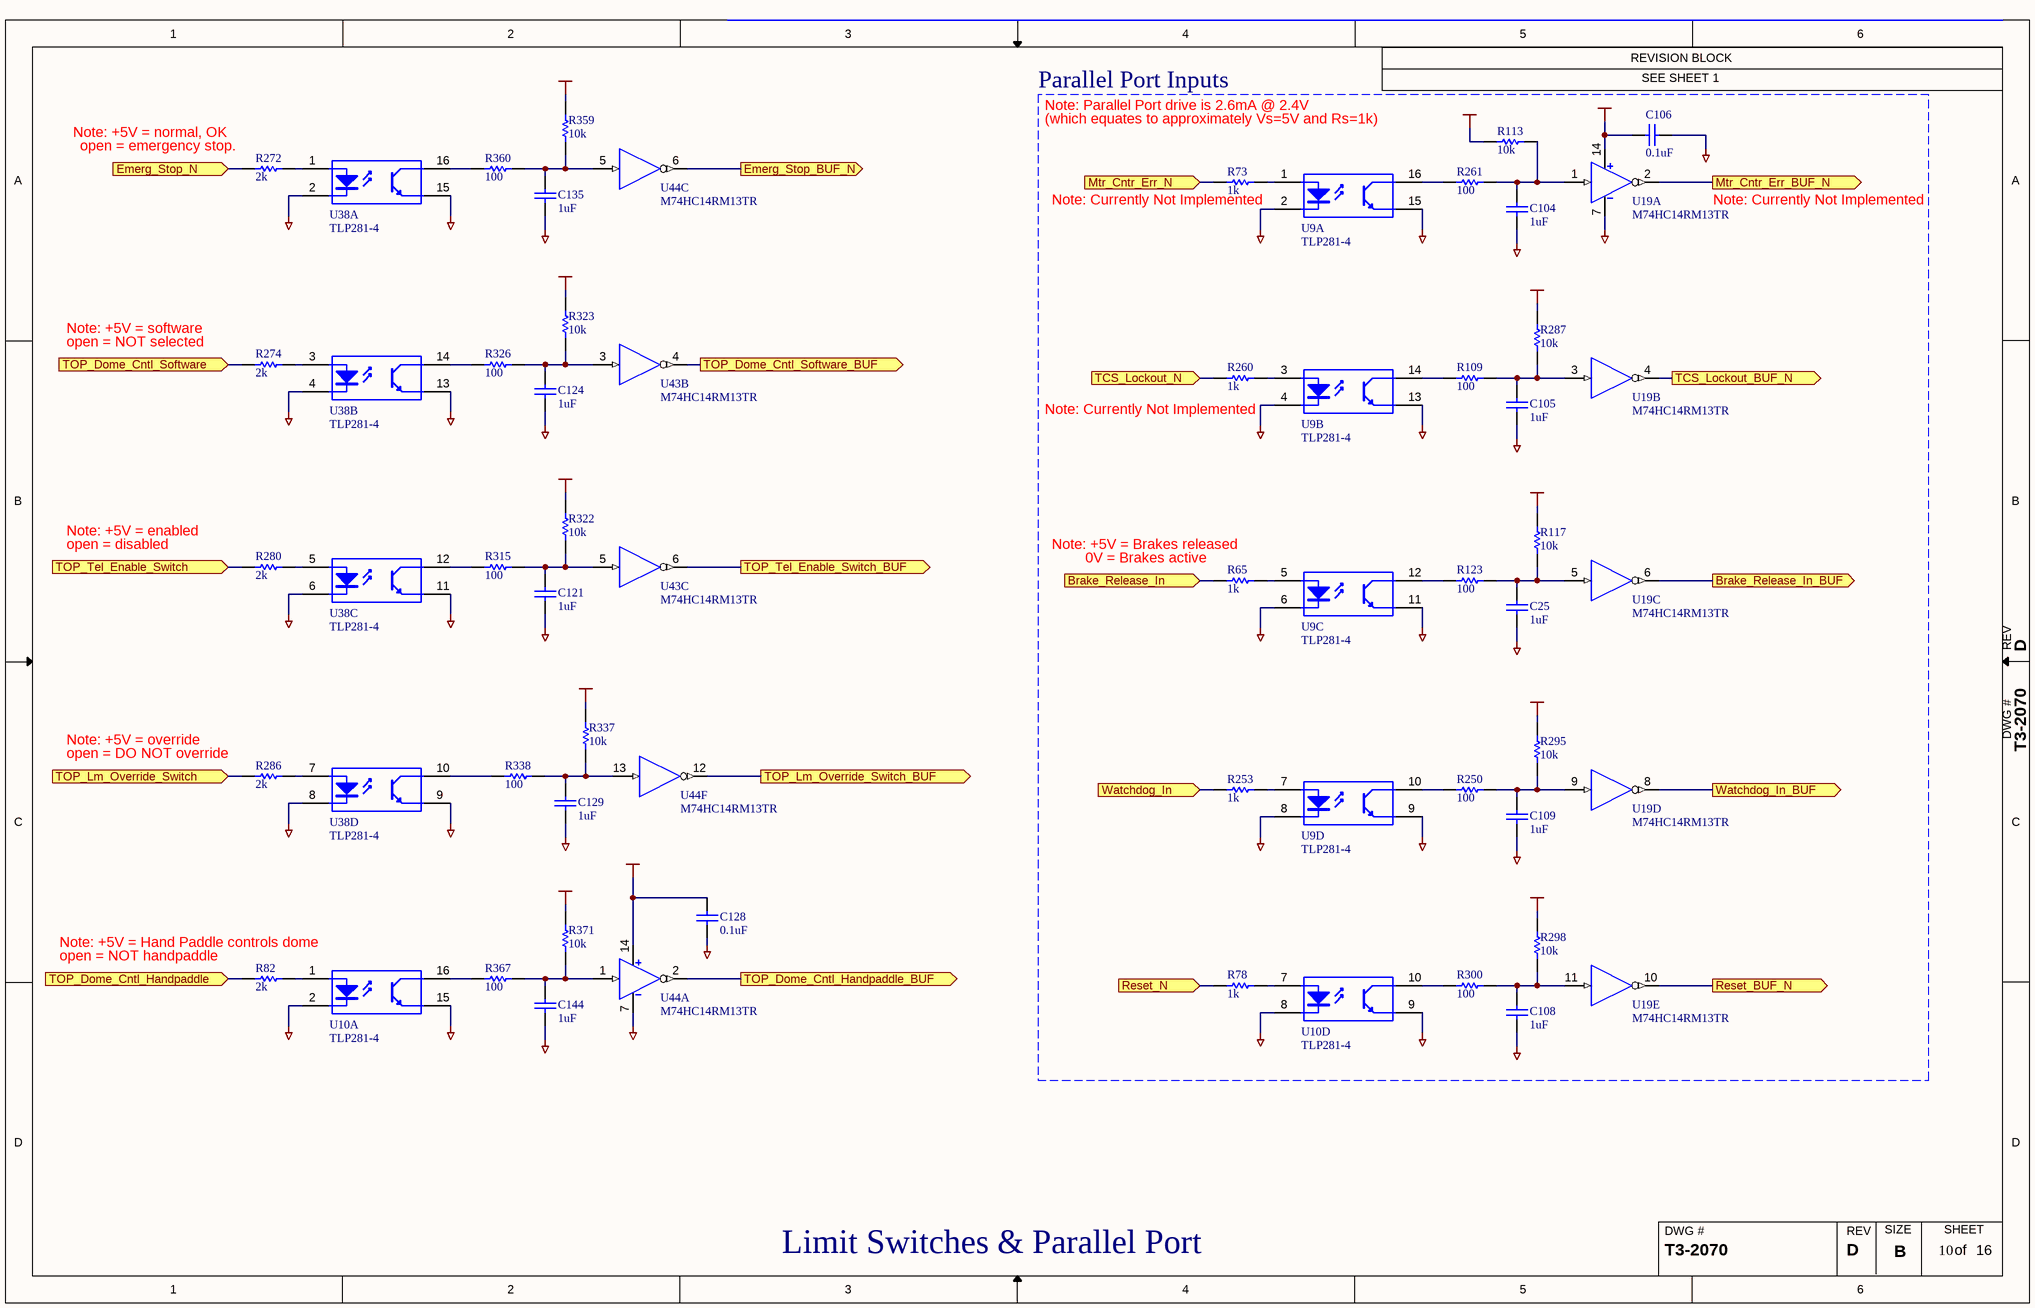
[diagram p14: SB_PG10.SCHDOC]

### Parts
C25  1uF  [1206]
C104  1uF  [1206]
C105  1uF  [1206]
C106  0.1uF  [1206]
C108  1uF  [1206]
C109  1uF  [1206]
C121  1uF  [1206]
C124  1uF  [1206]
C128  0.1uF  [1206]
C129  1uF  [1206]
C135  1uF  [1206]
C144  1uF  [1206]
R65  value 1k  [1206]  (hidden comment: 1000)
R73  value 1k  [1206]  (hidden comment: 1000)
R78  value 1k  [1206]  (hidden comment: 1000)
R82  value 2k  [1206]  (hidden comment: 2000)
R109  100  [1206]
R113  value 10k  [1206]  (hidden comment: 10000)
R117  value 10k  [1206]  (hidden comment: 10000)
R123  100  [1206]
R250  100  [1206]
R253  value 1k  [1206]  (hidden comment: 1000)
R260  value 1k  [1206]  (hidden comment: 1000)
R261  100  [1206]
R272  value 2k  [1206]  (hidden comment: 2000)
R274  value 2k  [1206]  (hidden comment: 2000)
R280  value 2k  [1206]  (hidden comment: 2000)
R286  value 2k  [1206]  (hidden comment: 2000)
R287  value 10k  [1206]  (hidden comment: 10000)
R295  value 10k  [1206]  (hidden comment: 10000)
R298  value 10k  [1206]  (hidden comment: 10000)
R300  100  [1206]
R315  100  [1206]
R322  value 10k  [1206]  (hidden comment: 10000)
R323  value 10k  [1206]  (hidden comment: 10000)
R326  100  [1206]
R337  value 10k  [1206]  (hidden comment: 10000)
R338  100  [1206]
R359  value 10k  [1206]  (hidden comment: 10000)
R360  100  [1206]
R367  100  [1206]
R371  value 10k  [1206]  (hidden comment: 10000)
U9  TLP281-4  [SOIC_16_C5.85]  (parts A,B,C,D of 4)
U10  TLP281-4  [SOIC_16_C5.85]  (parts A,D of 4)
U19  M74HC14RM13TR  [SOIC_14_Narrow]  (parts A,B,C,D,E of 6)
U38  TLP281-4  [SOIC_16_C5.85]  (parts A,B,C,D of 4)
U43  M74HC14RM13TR  [SOIC_14_Narrow]  (parts B,C of 6)
U44  M74HC14RM13TR  [SOIC_14_Narrow]  (parts A,C,F of 6)

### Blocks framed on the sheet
Parallel Port Inputs: C25 C104-C106 C108 C109 R65 R73 R78 R109 R113 R117 R123 R250 R253 R260 R261 R287 R295 R298 R300 U9 U10 U19

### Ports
Brake_Release_In (in), Brake_Release_In_BUF (out), Emerg_Stop_BUF_N (out), Emerg_Stop_N (in), Mtr_Cntr_Err_BUF_N (out), Mtr_Cntr_Err_N (in), Reset_BUF_N (out), Reset_N (in), TCS_Lockout_BUF_N (out), TCS_Lockout_N (in), TOP_Dome_Cntl_Handpaddle (in), TOP_Dome_Cntl_Handpaddle_BUF (out), TOP_Dome_Cntl_Software (in), TOP_Dome_Cntl_Software_BUF (out), TOP_Lm_Override_Switch (in), TOP_Lm_Override_Switch_BUF (out), TOP_Tel_Enable_Switch (in), TOP_Tel_Enable_Switch_BUF (out), Watchdog_In (in), Watchdog_In_BUF (out)

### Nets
+5V_DIG: C106.2 C128.2 R113.2 R117.2 R287.2 R295.2 R298.2 R322.2 R323.2 R337.2 R359.2 R371.2 U19.14(VDD) U44.14(VDD)
DGND: C25.1 C104.1 C105.1 C106.1 C108.1 C109.1 C121.1 C124.1 C128.1 C129.1 C135.1 C144.1 U9.9(E) U9.11(E) U9.13(E) U9.15(E) U10.9(E) U10.15(E) U19.7(GND) U38.9(E) U38.11(E) U38.13(E) U38.15(E) U44.7(GND)
PCGND: U9.2(K) U9.4(K) U9.6(K) U9.8(K) U10.8(K)
SEGND: U10.2(K) U38.2(K) U38.4(K) U38.6(K) U38.8(K)
Brake En In: R65.1 ; port Brake_Release_In
Brake_Release_In_BUF: U19.6(~{OUT}) ; port Brake_Release_In_BUF
Emerg Stop: R272.2 ; port Emerg_Stop_N
Emerg_Stop_BUF_N: U44.6(~{OUT}) ; port Emerg_Stop_BUF_N
Mtr Cntr Err: R73.1 ; port Mtr_Cntr_Err_N
Mtr_Cntr_Err_BUF: U19.2(~{OUT}) ; port Mtr_Cntr_Err_BUF_N
Reset: R78.1 ; port Reset_N
Reset_BUF_N: U19.10(~{OUT}) ; port Reset_BUF_N
TCS Lockout: R260.1 ; port TCS_Lockout_N
TCS_Lockout_BUF_N: U19.4(~{OUT}) ; port TCS_Lockout_BUF_N
TOP DomeCntl Handpaddle: R82.2 ; port TOP_Dome_Cntl_Handpaddle
TOP DomeCntl Software: R274.2 ; port TOP_Dome_Cntl_Software
TOP Lm Override Switch: R286.2 ; port TOP_Lm_Override_Switch
TOP Tel Enable Switch: R280.2 ; port TOP_Tel_Enable_Switch
TOP_Dome_Cntl_Handpaddle_BUF: U44.2(~{OUT}) ; port TOP_Dome_Cntl_Handpaddle_BUF
TOP_Dome_Cntl_Software_BUF: U43.4(~{OUT}) ; port TOP_Dome_Cntl_Software_BUF
TOP_Lm_Override_Switch_BUF: U44.12(~{OUT}) ; port TOP_Lm_Override_Switch_BUF
TOP_Tel_Enable_Switch_BUF: U43.6(~{OUT}) ; port TOP_Tel_Enable_Switch_BUF
Watchdog In: R253.1 ; port Watchdog_In
Watchdog_In_BUF: U19.8(~{OUT}) ; port Watchdog_In_BUF
NetC25_2: C25.2 R117.1 R123.1 U19.5(IN)
NetC104_2: C104.2 R113.1 R261.1 U19.1(IN)
NetC105_2: C105.2 R109.1 R287.1 U19.3(IN)
NetC108_2: C108.2 R298.1 R300.1 U19.11(IN)
NetC109_2: C109.2 R250.1 R295.1 U19.9(IN)
NetC121_2: C121.2 R315.1 R322.1 U43.5(IN)
NetC124_2: C124.2 R323.1 R326.1 U43.3(IN)
NetC129_2: C129.2 R337.1 R338.1 U44.13(IN)
NetC135_2: C135.2 R359.1 R360.1 U44.5(IN)
NetC144_2: C144.2 R367.1 R371.1 U44.1(IN)
NetR65_2: R65.2 U9.5(A)
NetR73_2: R73.2 U9.1(A)
NetR78_2: R78.2 U10.7(A)
NetR82_1: R82.1 U10.1(A)
NetR109_2: R109.2 U9.14(C)
NetR123_2: R123.2 U9.12(C)
NetR250_2: R250.2 U9.10(C)
NetR253_2: R253.2 U9.7(A)
NetR260_2: R260.2 U9.3(A)
NetR261_2: R261.2 U9.16(C)
NetR272_1: R272.1 U38.1(A)
NetR274_1: R274.1 U38.3(A)
NetR280_1: R280.1 U38.5(A)
NetR286_1: R286.1 U38.7(A)
NetR300_2: R300.2 U10.10(C)
NetR315_2: R315.2 U38.12(C)
NetR326_2: R326.2 U38.14(C)
NetR338_2: R338.2 U38.10(C)
NetR360_2: R360.2 U38.16(C)
NetR367_2: R367.2 U10.16(C)

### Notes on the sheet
- Note: Parallel Port drive is 2.6mA @ 2.4V
- (near R272) Note: +5V = normal, OK
- (near R272) open = emergency stop.
- (which equates to approximately Vs=5V and Rs=1k)
- (near R73) Note: Currently Not Implemented
- Note: Currently Not Implemented
- (near R274) Note: +5V = software
- (near R274) open = NOT selected
- Note: +5V = enabled
- open = disabled
- (near R65) Note: +5V = Brakes released
- (near R65) 0V = Brakes active
- (near R286) Note: +5V = override
- (near R286) open = DO NOT override
- Note: +5V = Hand Paddle controls dome
- (near R82) open = NOT handpaddle
- Limit Switches & Parallel Port

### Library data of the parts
C25 C104 C105 C108 C109 C121 C124 C129 C135 C144 = 1uF: as C131 on sheet SB_PG7
C106 C128 = 0.1uF: as C39 on sheet SB_PG7
R65 R73 R78 R253 R260 = 1000: as R334 on sheet SB_PG7
R82 R272 R274 R280 R286 = 2000: as R348 on sheet SB_PG7
R109 R123 R250 R261 R300 R315 R326 R338 R360 R367 = 100: as R356 on sheet SB_PG7
R113 R117 R287 R295 R298 R322 R323 R337 R359 R371 = 10000: as R171 on sheet SB_PG7
U9 U10 U38 = TLP281-4: Photocoupler; Manufacturer: Toshiba
U19 U43 U44 = M74HC14RM13TR: as U28 on sheet SB_PG7

## Sheet SB_PG16.SCHDOC: (Title)
size B; Engineer: (Engineer); Organization: Institute for Astronomy; Address1: 640 N. Aohoku Place; Address2: Hilo, HI 96720; DocumentNumber: T3-2070; Revision: D; SheetNumber: 16; SheetTotal: 16
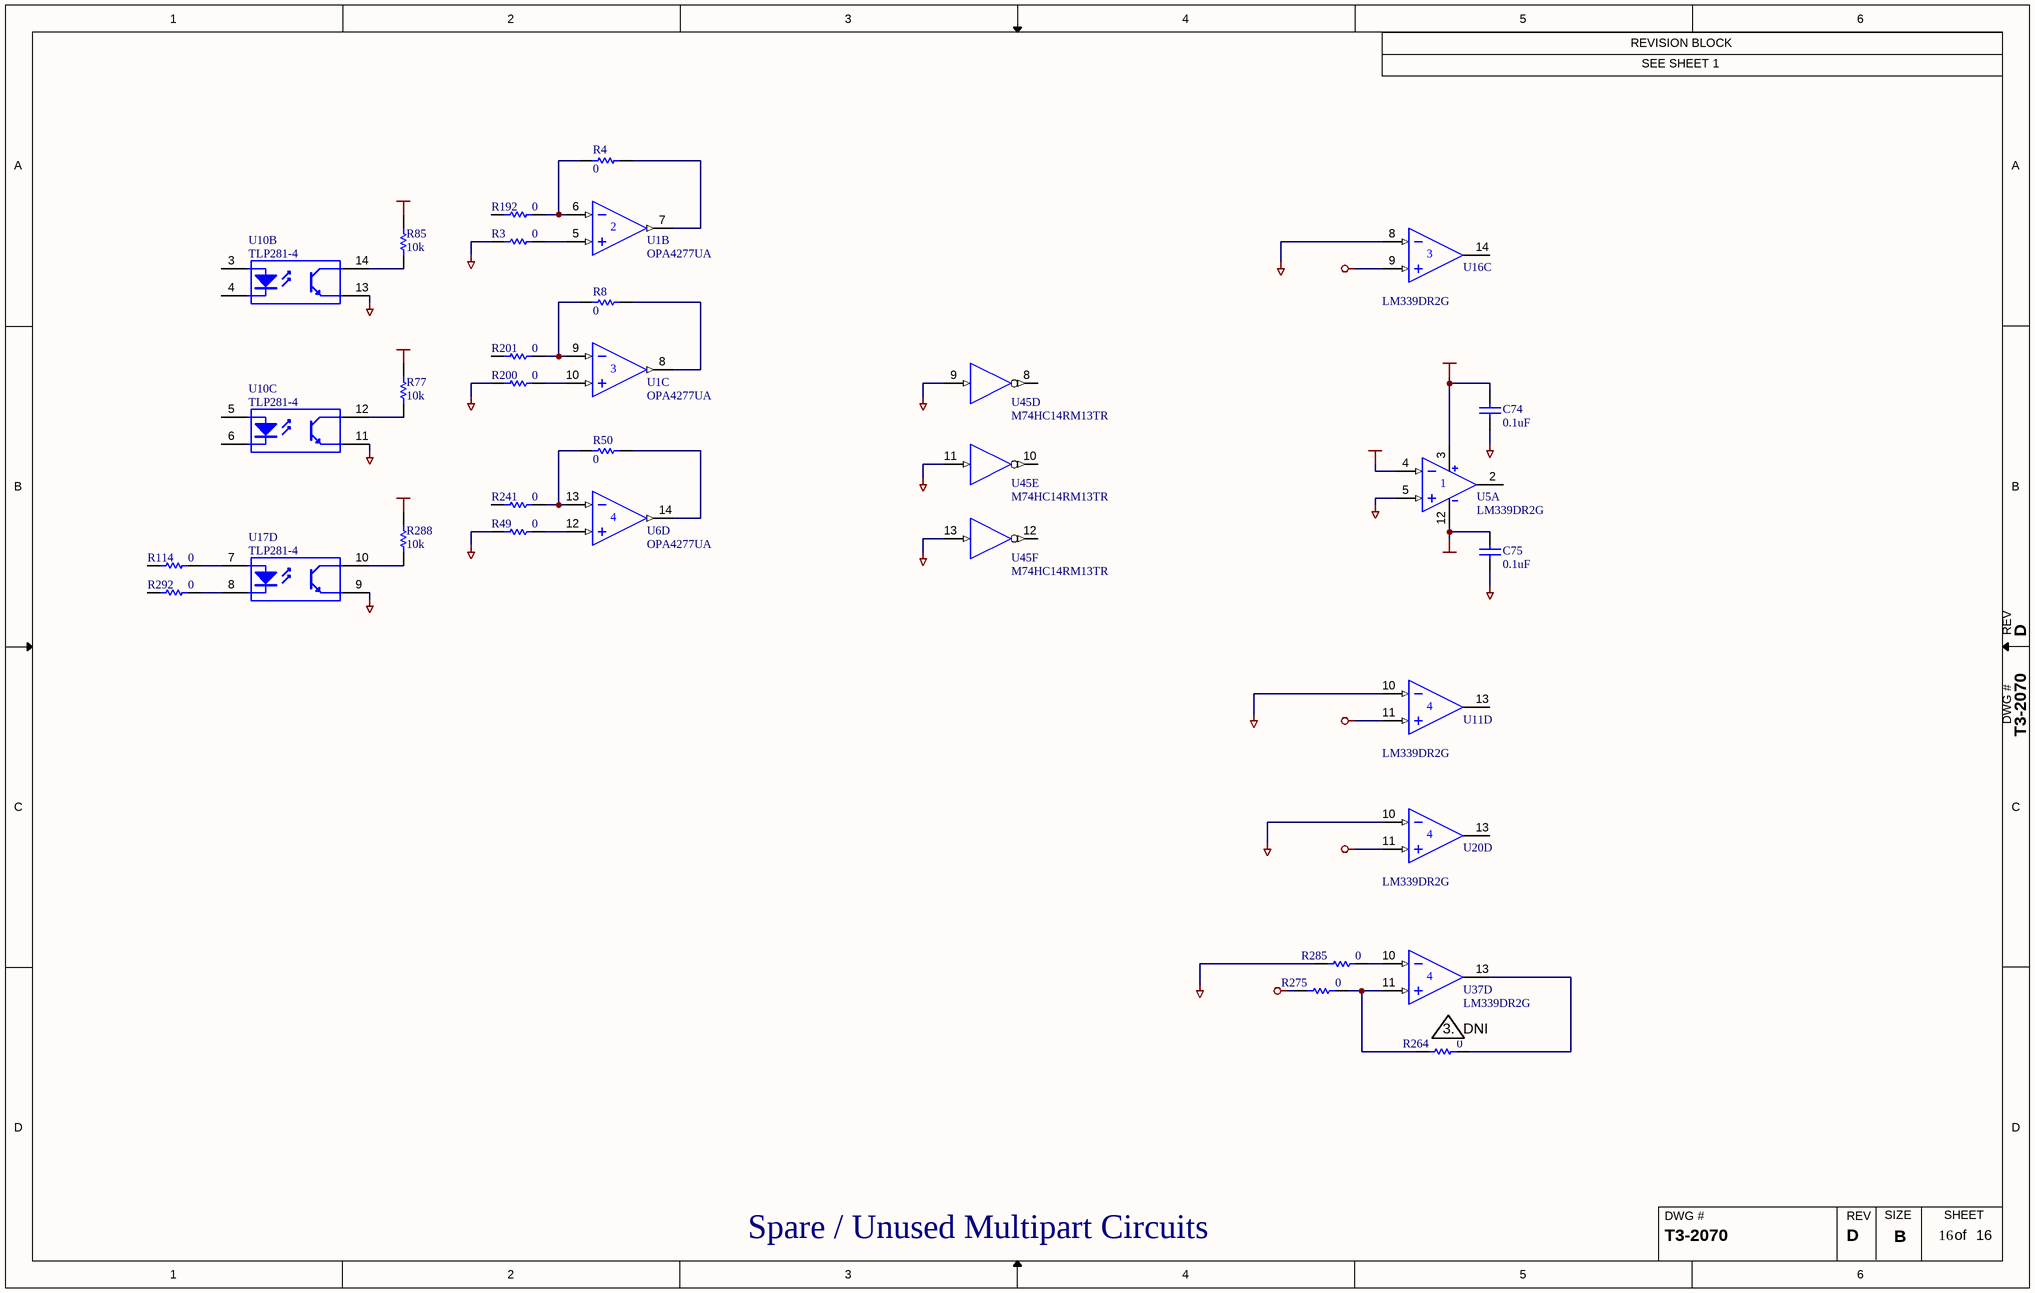
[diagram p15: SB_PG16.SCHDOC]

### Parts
(Parts that share a designator on the sheet are numbered #1, #2 ... from top to bottom, then left to right.)
C74  0.1uF  [1206]
C75  0.1uF  [1206]
Flag?#49  Flag#: 3.  Note: DNI  (graphical)
R3  value 0  [1206]  (hidden comment: 0_jumper)
R4  value 0  [1206]  (hidden comment: 0_jumper)
R8  value 0  [1206]  (hidden comment: 0_jumper)
R49  value 0  [1206]  (hidden comment: 0_jumper)
R50  value 0  [1206]  (hidden comment: 0_jumper)
R77  value 10k  [1206]  (hidden comment: 10000)
R85  value 10k  [1206]  (hidden comment: 10000)
R114  value 0  [1206]  (hidden comment: 0_jumper)
R192  value 0  [1206]  (hidden comment: 0_jumper)
R200  value 0  [1206]  (hidden comment: 0_jumper)
R201  value 0  [1206]  (hidden comment: 0_jumper)
R241  value 0  [1206]  (hidden comment: 0_jumper)
R264  value 0  [1206]  (hidden comment: 0_jumper)  (no BOM)
R275  value 0  [1206]  (hidden comment: 0_jumper)
R285  value 0  [1206]  (hidden comment: 0_jumper)
R288  value 10k  [1206]  (hidden comment: 10000)
R292  value 0  [1206]  (hidden comment: 0_jumper)
U1  OPA4277UA  [SOIC_14_Narrow]  (parts B,C of 4)
U5  LM339DR2G  [SOIC_14_Narrow]  (part A of 4)
U6  OPA4277UA  [SOIC_14_Narrow]  (part D of 4)
U10  TLP281-4  [SOIC_16_C5.85]  (parts B,C of 4)
U11  LM339DR2G  [SOIC_14_Narrow]  (part D of 4)
U16  LM339DR2G  [SOIC_14_Narrow]  (part C of 4)
U17  TLP281-4  [SOIC_16_C5.85]  (part D of 4)
U20  LM339DR2G  [SOIC_14_Narrow]  (part D of 4)
U37  LM339DR2G  [SOIC_14_Narrow]  (part D of 4)
U45  M74HC14RM13TR  [SOIC_14_Narrow]  (parts D,E,F of 6)

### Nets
+5_VREF: R275.1 U11.11(IN+) U20.11(IN+)
+5V_DIG: R77.2 R85.2 R288.2
+15V: C74.2 U5.3(V+) U5.4(IN-)
-5_VREF: U16.9(IN+)
-15V: C75.2 U5.12(V-)
AGND: C74.1 C75.1 R3.1 R49.1 R200.1 R285.1 U5.5(IN+) U11.10(IN-) U16.8(IN-) U20.10(IN-)
DGND: U10.11(E) U10.13(E) U17.9(E) U45.9(IN) U45.11(IN) U45.13(IN)
NetR3_2: R3.2 U1.5(IN+)
NetR4_1: R4.1 R192.2 U1.6(IN-)
NetR4_2: R4.2 U1.7(OUT)
NetR8_1: R8.1 R201.2 U1.9(IN-)
NetR8_2: R8.2 U1.8(OUT)
NetR49_2: R49.2 U6.12(IN+)
NetR50_1: R50.1 R241.2 U6.13(IN-)
NetR50_2: R50.2 U6.14(OUT)
NetR77_1: R77.1 U10.12(C)
NetR85_1: R85.1 U10.14(C)
NetR114_2: R114.2 U17.7(A)
NetR200_2: R200.2 U1.10(IN+)
NetR264_1: R264.1 R275.2 U37.11(IN+)
NetR264_2: R264.2 U37.13(OUT)
NetR285_2: R285.2 U37.10(IN-)
NetR288_1: R288.1 U17.10(C)
NetR292_2: R292.2 U17.8(K)

Not connected (* = marked no-connect by the designer): R114 1; R192 1; R201 1; R241 1; R292 1; U5 2(OUT); U10 3(A) 4(K) 5(A) 6(K); U11 13(OUT); U16 14(OUT); U20 13(OUT); U45 8(~{OUT}) 10(~{OUT}) 12(~{OUT})

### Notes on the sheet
- Spare / Unused Multipart Circuits

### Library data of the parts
C74 C75 = 0.1uF: as C39 on sheet SB_PG7
Flag?#49 = Flag
R3 R4 R8 R49 R50 R114 R192 R200 R201 R241 R264 R275 R285 R292 = 0_jumper: as R172 on sheet SB_PG7
R77 R85 R288 = 10000: as R171 on sheet SB_PG7
U1 U6 = OPA4277UA: QUAD PRECISION OPAMP 14-SOIC; Manufacturer: Texas Instruments
U5 U11 U16 U20 U37 = LM339DR2G: Quad Comparator; Manufacturer: ON Semiconductor
U10 U17 = TLP281-4: Photocoupler; Manufacturer: Toshiba
U45 = M74HC14RM13TR: as U28 on sheet SB_PG7

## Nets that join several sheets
24VGND: SB_PG1 (J3.49), SB_PG8 (TP35.1)
+5_VREF: SB_PG4 (R35.2), SB_PG13 (R100.1 R225.1), SB_PG5 (R258.2), SB_PG2 (C19.2 D8.1 R46.1), SB_PG11 (R92.1 R293.1), SB_PG12 (R277.1), SB_PG14 (R268.1 R282.1), SB_PG15 (R79.1 R102.1), SB_PG16 (R275.1 U11.11 U20.11)
+5V_DIG: SB_PG1 (J5.13), SB_PG13 (R143.2 R170.2), SB_PG6 (35 pins), SB_PG3 (C120.2 U24.4 U24.16), SB_PG2 (5 pins), SB_PG11 (R312.2 R324.2), SB_PG12 (C118.2 R132.2 U40.14), SB_PG14 (R130.2 R328.2), SB_PG15 (R156.2 R317.2), SB_PG7 (6 pins), SB_PG8 (6 pins), SB_PG9 (18 pins), SB_PG10 (14 pins), SB_PG16 (R77.2 R85.2 R288.2)
+5V_SE: SB_PG2 (5 pins), SB_PG9 (12 pins)
+5V_WD: SB_PG2 (5 pins), SB_PG7 (R369.2 R380.2)
+15V: SB_PG4 (5 pins), SB_PG13 (8 pins), SB_PG5 (5 pins), SB_PG2 (6 pins), SB_PG11 (8 pins), SB_PG12 (6 pins), SB_PG14 (6 pins), SB_PG15 (10 pins), SB_PG16 (C74.2 U5.3 U5.4)
-5_VREF: SB_PG4 (R231.1), SB_PG13 (U5.8 U16.4), SB_PG5 (R263.1), SB_PG2 (C3.2 D1.2 R17.2), SB_PG11 (U11.4 U20.4), SB_PG12 (U37.4), SB_PG14 (U14.4 U15.8), SB_PG15 (U12.4 U15.4), SB_PG16 (U16.9)
-15V: SB_PG4 (C68.2 C71.2 U3.11 U4.11), SB_PG13 (C52.2 C102.2 U1.11 U16.12), SB_PG5 (C15.2 C23.2 U2.11 U8.11), SB_PG2 (6 pins), SB_PG11 (C99.2 C107.2 U11.12 U20.12), SB_PG12 (C83.2 C91.2 U6.11 U37.12), SB_PG14 (C100.2 U14.12), SB_PG15 (6 pins), SB_PG16 (C75.2 U5.12)
AGND: SB_PG1 (9 pins), SB_PG4 (25 pins), SB_PG13 (12 pins), SB_PG5 (25 pins), SB_PG2 (18 pins), SB_PG11 (12 pins), SB_PG12 (8 pins), SB_PG14 (10 pins), SB_PG15 (14 pins), SB_PG16 (10 pins)
DGND: SB_PG1 (J5.15), SB_PG4 (U17.11), SB_PG13 (C32.1 C40.1 U17.15 U22.9), SB_PG5 (U17.13), SB_PG6 (52 pins), SB_PG3 (8 pins), SB_PG2 (9 pins), SB_PG11 (C115.1 C122.1 U22.11 U22.13), SB_PG12 (C26.1 C118.1 U22.15 U40.7), SB_PG14 (C28.1 C125.1 U21.11 U21.13), SB_PG15 (C35.1 C119.1 U21.9 U21.15), SB_PG7 (12 pins), SB_PG8 (7 pins), SB_PG9 (30 pins), SB_PG10 (24 pins), SB_PG16 (6 pins)
EGND: SB_PG1 (J5.9 J5.11), SB_PG3 (R153.2)
PCGND: SB_PG1 (J3.50), SB_PG2 (TP29.1), SB_PG10 (5 pins)
SEGND: SB_PG2 (7 pins), SB_PG8 (U23.2), SB_PG10 (5 pins)
WDGND: SB_PG2 (7 pins), SB_PG7 (16 pins)
15V_Rtn: SB_PG1 (J1.11 J1.12 J2.4), SB_PG2 (C1.2 C2.1 L2.6)
24V: SB_PG1 (J4.1), SB_PG8 (D28.K U41.6)
+5V_DIG_Raw: SB_PG1 (J1.5 J1.6 J2.1), SB_PG2 (5 pins)
+5V_DIG_Rtn: SB_PG1 (J1.7 J1.8 J2.2), SB_PG2 (5 pins)
+5V_SE_Raw: SB_PG1 (J1.1), SB_PG2 (5 pins)
+5V_SE_Rtn: SB_PG1 (J1.2), SB_PG2 (5 pins)
+5V_WD_Raw: SB_PG1 (J1.3), SB_PG2 (5 pins)
+5V_WD_Rtn: SB_PG1 (J1.4), SB_PG2 (5 pins)
+15V_Raw: SB_PG1 (J1.9 J1.10 J2.3), SB_PG2 (C2.2 L2.5 R194.1)
-15V_Raw: SB_PG1 (J1.13 J1.14 J2.5), SB_PG2 (C1.1 L2.8 R1.1)
Brake En In: SB_PG1 (J3.21), SB_PG10 (R65.1)
Brake Enable Relay: SB_PG1 (J4.2), SB_PG8 (D10.A U23.4)
Brake_Release_In_BUF: SB_PG6 (U32.42), SB_PG10 (U19.6)
CPLD_Clk: SB_PG6 (U28.12), SB_PG7 (R348.1 U28.3)
Dec Emerg N: SB_PG1 (J3.38), SB_PG9 (U13.8)
Dec Emerg N Latch: SB_PG1 (J4.37), SB_PG6 (U33.14)
Dec Emerg S: SB_PG1 (J3.39), SB_PG9 (U18.4)
Dec Emerg S Latch: SB_PG1 (J4.38), SB_PG6 (U33.13)
Dec OS Latch: SB_PG1 (J4.19), SB_PG6 (U27.16)
Dec Stop N: SB_PG1 (J3.36), SB_PG9 (U39.6)
Dec Stop N Latch: SB_PG1 (J4.35), SB_PG6 (U33.16)
Dec Stop S: SB_PG1 (J3.37), SB_PG9 (U13.4)
Dec Stop S Latch: SB_PG1 (J4.36), SB_PG6 (U33.15)
Dec Vel Feedback: SB_PG1 (J3.17), SB_PG4 (R226.2 TP16.1 U3.14), SB_PG13 (R196.1)
Dec_Emerg_North_BUF_N: SB_PG6 (U32.14), SB_PG9 (U42.8)
Dec_Emerg_South_BUF_N: SB_PG6 (U32.12), SB_PG9 (U42.12)
Dec_Lab_Select: SB_PG4 (U17.12), SB_PG5 (U17.14), SB_PG6 (R181.1 U32.41)
Dec_Overspeed_N: SB_PG13 (TP47.1 U45.6), SB_PG6 (U32.55)
Dec_Stop_North_BUF_N: SB_PG6 (U32.9), SB_PG9 (U43.2)
Dec_Stop_South_BUF_N: SB_PG6 (U32.16), SB_PG9 (U42.4)
Dome1 Current: SB_PG1 (J3.28), SB_PG11 (R252.1 TP22.1)
Dome1 OC Latch: SB_PG1 (J4.24), SB_PG6 (U27.11)
Dome1_Overcurrent_N: SB_PG6 (U32.30), SB_PG11 (TP44.1 U40.4)
Dome2 Current: SB_PG1 (J3.29), SB_PG11 (R76.1 TP19.1)
Dome2 OC Latch: SB_PG1 (J4.25), SB_PG6 (U30.18)
Dome2_Overcurrent_N: SB_PG6 (U32.32), SB_PG11 (TP45.1 U40.6)
Dome3 Current: SB_PG1 (J3.30), SB_PG12 (R239.1 TP18.1)
Dome3 OC Latch: SB_PG1 (J4.26), SB_PG6 (U30.17)
Dome3_Overcurrent_N: SB_PG6 (U32.29), SB_PG12 (TP46.1 U40.2)
Dome Amp: SB_PG1 (J4.6), SB_PG8 (D12.K R151.1)
Dome Amp Enable & Therm Stat Latch: SB_PG1 (J4.42), SB_PG6 (U35.17)
Dome Amp Ret: SB_PG1 (J4.7), SB_PG8 (D12.A U25.13)
Dome_Amp_Enable_&_Therm_Stat: SB_PG6 (U32.8), SB_PG8 (U43.12)
Dome_Amp_Enable_N: SB_PG6 (U32.23), SB_PG8 (R146.1 R150.2)
East Current: SB_PG1 (J3.25), SB_PG14 (R58.1 TP20.1)
East Drive+: SB_PG1 (J3.1), SB_PG5 (C57.2 R16.1 TP12.1)
East Drive-: SB_PG1 (J3.2), SB_PG5 (C54.2 R15.1 TP11.1)
East OC Latch: SB_PG1 (J4.21), SB_PG6 (U27.14)
East Tach Out: SB_PG1 (J4.3), SB_PG5 (6 pins)
East Vel In: SB_PG1 (J3.13), SB_PG5 (R220.2)
East Vel Out: SB_PG1 (J4.10), SB_PG5 (C77.2 R43.2)
East_Encoder_BUF: SB_PG1 (J5.3), SB_PG3 (R141.1 R321.2)
East_Encoder_In: SB_PG1 (J5.6), SB_PG3 (R149.1 R168.1)
East_Encoder_Rtn: SB_PG1 (J5.8), SB_PG3 (R167.1 R332.1)
East_Overcurrent_N: SB_PG6 (U32.27), SB_PG14 (TP42.1 U40.12)
Emerg Stop: SB_PG1 (J3.40), SB_PG8 (R310.2), SB_PG10 (R272.2)
Emerg Stop Latch: SB_PG1 (J4.27), SB_PG6 (U30.16)
Emerg_Stop_BUF_N: SB_PG6 (U32.18), SB_PG10 (U44.6)
HA Emerg E: SB_PG1 (J3.35), SB_PG9 (U39.2)
HA Emerg E Latch: SB_PG1 (J4.34), SB_PG6 (U33.17)
HA Emerg W: SB_PG1 (J3.34), SB_PG9 (U18.6)
HA Emerg W Latch: SB_PG1 (J4.33), SB_PG6 (U33.18)
HA OS Latch: SB_PG1 (J4.18), SB_PG6 (U27.17)
HA Stop E: SB_PG1 (J3.33), SB_PG9 (U18.2)
HA Stop E Latch: SB_PG1 (J4.32), SB_PG6 (U30.11)
HA Stop W: SB_PG1 (J3.32), SB_PG9 (U13.6)
HA Stop W Latch: SB_PG1 (J4.31), SB_PG6 (U30.12)
HA Vel Feedback: SB_PG1 (J3.18), SB_PG13 (R7.1), SB_PG5 (R75.2 TP23.1 U8.14)
HA_Emerg_East_BUF_N: SB_PG6 (U32.1), SB_PG9 (U43.8)
HA_Emerg_West_BUF_N: SB_PG6 (U32.54), SB_PG9 (U45.4)
HA_Overspeed_N: SB_PG13 (TP39.1 U40.8), SB_PG6 (U32.28)
HA_Stop_East_BUF_N: SB_PG6 (U32.13), SB_PG9 (U42.10)
HA_Stop_West_BUF_N: SB_PG6 (U32.15), SB_PG9 (U42.6)
Horizon Stop: SB_PG1 (J3.31), SB_PG9 (U13.2)
Horizon Stop Latch: SB_PG1 (J4.39), SB_PG6 (U33.12)
Horizon_Stop_BUF_N: SB_PG6 (U32.17), SB_PG9 (U42.2)
HP Stop: SB_PG1 (J3.44), SB_PG9 (U18.8)
HP Stop Latch: SB_PG1 (J4.28), SB_PG6 (U30.15)
HP_Stop_BUF_N: SB_PG6 (U32.53), SB_PG9 (U45.2)
Lab Switch Select Status: SB_PG1 (J4.44), SB_PG6 (U35.15)
Mtr Cntr Err: SB_PG1 (J3.19), SB_PG10 (R73.1)
Mtr Cntr Err Latch: SB_PG1 (J4.29), SB_PG6 (U30.14)
Mtr_Cntr_Err_BUF: SB_PG6 (U32.36), SB_PG10 (U19.2)
North Current: SB_PG1 (J3.26), SB_PG15 (R248.1 TP17.1)
North Drive+: SB_PG1 (J3.10), SB_PG4 (C60.2 R10.1 TP6.1)
North Drive-: SB_PG1 (J3.11), SB_PG4 (C59.2 R9.1 TP5.1)
North OC Latch: SB_PG1 (J4.22), SB_PG6 (U27.13)
North Tach Out: SB_PG1 (J4.47), SB_PG4 (6 pins)
North Vel In: SB_PG1 (J3.16), SB_PG4 (R19.1)
North Vel Out: SB_PG1 (J4.16), SB_PG4 (C76.2 R36.2)
North_Encoder_BUF: SB_PG1 (J5.5), SB_PG3 (R139.1 R319.2)
North_Encoder_In: SB_PG1 (J5.10), SB_PG3 (R154.1 R351.1)
North_Encoder_Rtn: SB_PG1 (J5.12), SB_PG3 (R329.1 R350.1)
North_Overcurrent_N: SB_PG6 (U32.33), SB_PG15 (TP40.1 U40.10)
Red_Tel_Brake_Release_&_Amp_Enable: SB_PG6 (U32.11), SB_PG8 (R128.1 R311.2)
Reset: SB_PG1 (J3.23), SB_PG10 (R78.1)
Reset_BUF_N: SB_PG6 (U32.35), SB_PG10 (U19.10)
SB OPTO22 Rtn: SB_PG1 (J4.46), SB_PG6 (R374.2 R376.2)
SB_Clock_WD_Err_Latch: SB_PG1 (J4.41), SB_PG6 (U35.18)
SB_Clock_WD_Err_N: SB_PG6 (U32.25), SB_PG7 (U28.2)
South Current: SB_PG1 (J3.27), SB_PG15 (R247.1 TP15.1)
South Drive+: SB_PG1 (J3.7), SB_PG4 (C55.2 R12.1 TP8.1)
South Drive-: SB_PG1 (J3.8), SB_PG4 (C58.2 R11.1 TP7.1)
South OS Latch: SB_PG1 (J4.23), SB_PG6 (U27.12)
South Tach Out: SB_PG1 (J4.9), SB_PG4 (6 pins)
South Vel In: SB_PG1 (J3.15), SB_PG4 (R230.2)
South Vel Out: SB_PG1 (J4.14), SB_PG4 (C67.2 R215.2)
South_Encoder_BUF: SB_PG1 (J5.7), SB_PG3 (R138.1 R318.2)
South_Encoder_In: SB_PG1 (J5.14), SB_PG3 (R166.1 R330.1)
South_Encoder_Rtn: SB_PG1 (J5.16), SB_PG3 (R155.1 R165.1)
South_Overcurrent_N: SB_PG6 (U32.20), SB_PG15 (TP41.1 U44.4)
SPARE1_BUF_N: SB_PG6 (U32.40), SB_PG9 (U44.8)
Spare In 1: SB_PG1 (J3.45), SB_PG9 (U39.4)
Spare Latch Out 1: SB_PG1 (J4.45), SB_PG6 (U35.14)
System Power Status: SB_PG1 (J3.46), SB_PG9 (U39.8)
System_Power_Status_BUF_N: SB_PG6 (U32.58), SB_PG9 (U44.10)
TCS Lockout: SB_PG1 (J3.20), SB_PG10 (R260.1)
TCS Lockout Latch: SB_PG1 (J4.30), SB_PG6 (U30.13)
TCS_Lockout_BUF_N: SB_PG6 (U32.37), SB_PG10 (U19.4)
Tel Amp: SB_PG1 (J4.4), SB_PG8 (D11.K R327.1)
Tel Amp Enable & Therm Stat Latch: SB_PG1 (J4.43), SB_PG6 (U35.16)
Tel Amp Ret: SB_PG1 (J4.5), SB_PG8 (D11.A U25.15)
Tel_Amp_Enable_&_Therm_Stat: SB_PG6 (U32.6), SB_PG8 (U43.10)
Tel_Brake_Release_&_Amp_Enable_N: SB_PG6 (U32.3), SB_PG8 (R142.2 R144.2)
TOP Brake Enable Out: SB_PG1 (J4.50), SB_PG6 (U35.11)
TOP DomeCntl Handpaddle: SB_PG1 (J3.48), SB_PG10 (R82.2)
TOP DomeCntl Software: SB_PG1 (J3.41), SB_PG10 (R274.2)
TOP Lm Override Switch: SB_PG1 (J3.43), SB_PG10 (R286.2)
TOP TCS Enable: SB_PG1 (J4.49), SB_PG6 (U35.12)
TOP Tel Enable Switch: SB_PG1 (J3.42), SB_PG10 (R280.2)
TOP_Dome_Cntl_Handpaddle_BUF: SB_PG6 (U32.50), SB_PG10 (U44.2)
TOP_Dome_Cntl_Software_BUF: SB_PG6 (U32.10), SB_PG10 (U43.4)
TOP_Lm_Override_Switch_BUF: SB_PG6 (U32.56), SB_PG10 (U44.12)
TOP_Tel_Enable_Switch_BUF: SB_PG6 (U32.4), SB_PG10 (U43.6)
Watchdog In: SB_PG1 (J3.22), SB_PG10 (R253.1)
Watchdog Timer Latch: SB_PG1 (J4.40), SB_PG6 (U33.11)
Watchdog_In_BUF: SB_PG7 (R349.1 U28.5), SB_PG10 (U19.8)
Watchdog_Timer_Error_N: SB_PG6 (U32.39), SB_PG7 (U28.8)
West Current: SB_PG1 (J3.24), SB_PG14 (R61.1 TP21.1)
West Drive+: SB_PG1 (J3.4), SB_PG5 (C56.2 R14.1 TP10.1)
West Drive-: SB_PG1 (J3.5), SB_PG5 (C53.2 R13.1 TP9.1)
West OC Latch: SB_PG1 (J4.20), SB_PG6 (U27.15)
West Tach Out: SB_PG1 (J4.8), SB_PG5 (6 pins)
West Vel In: SB_PG1 (J3.14), SB_PG5 (R256.1)
West Vel Out: SB_PG1 (J4.12), SB_PG5 (C92.2 R80.2)
West_Encoder_BUF: SB_PG1 (J5.1), SB_PG3 (R140.1 R320.2)
West_Encoder_In: SB_PG1 (J5.2), SB_PG3 (R148.1 R353.1)
West_Encoder_Rtn: SB_PG1 (J5.4), SB_PG3 (R331.1 R352.1)
West_Overcurrent_N: SB_PG6 (U32.49), SB_PG14 (TP43.1 U19.12)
